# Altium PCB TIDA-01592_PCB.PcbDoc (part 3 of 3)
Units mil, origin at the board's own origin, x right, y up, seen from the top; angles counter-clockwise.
Board outline 2047.24 x 4291.34 mil, 4 copper layers (Top Layer, GND, PWR, Bottom Layer), stack 61.6 mil thick; 218 components, 89 nets, 503 pads, 366 vias.
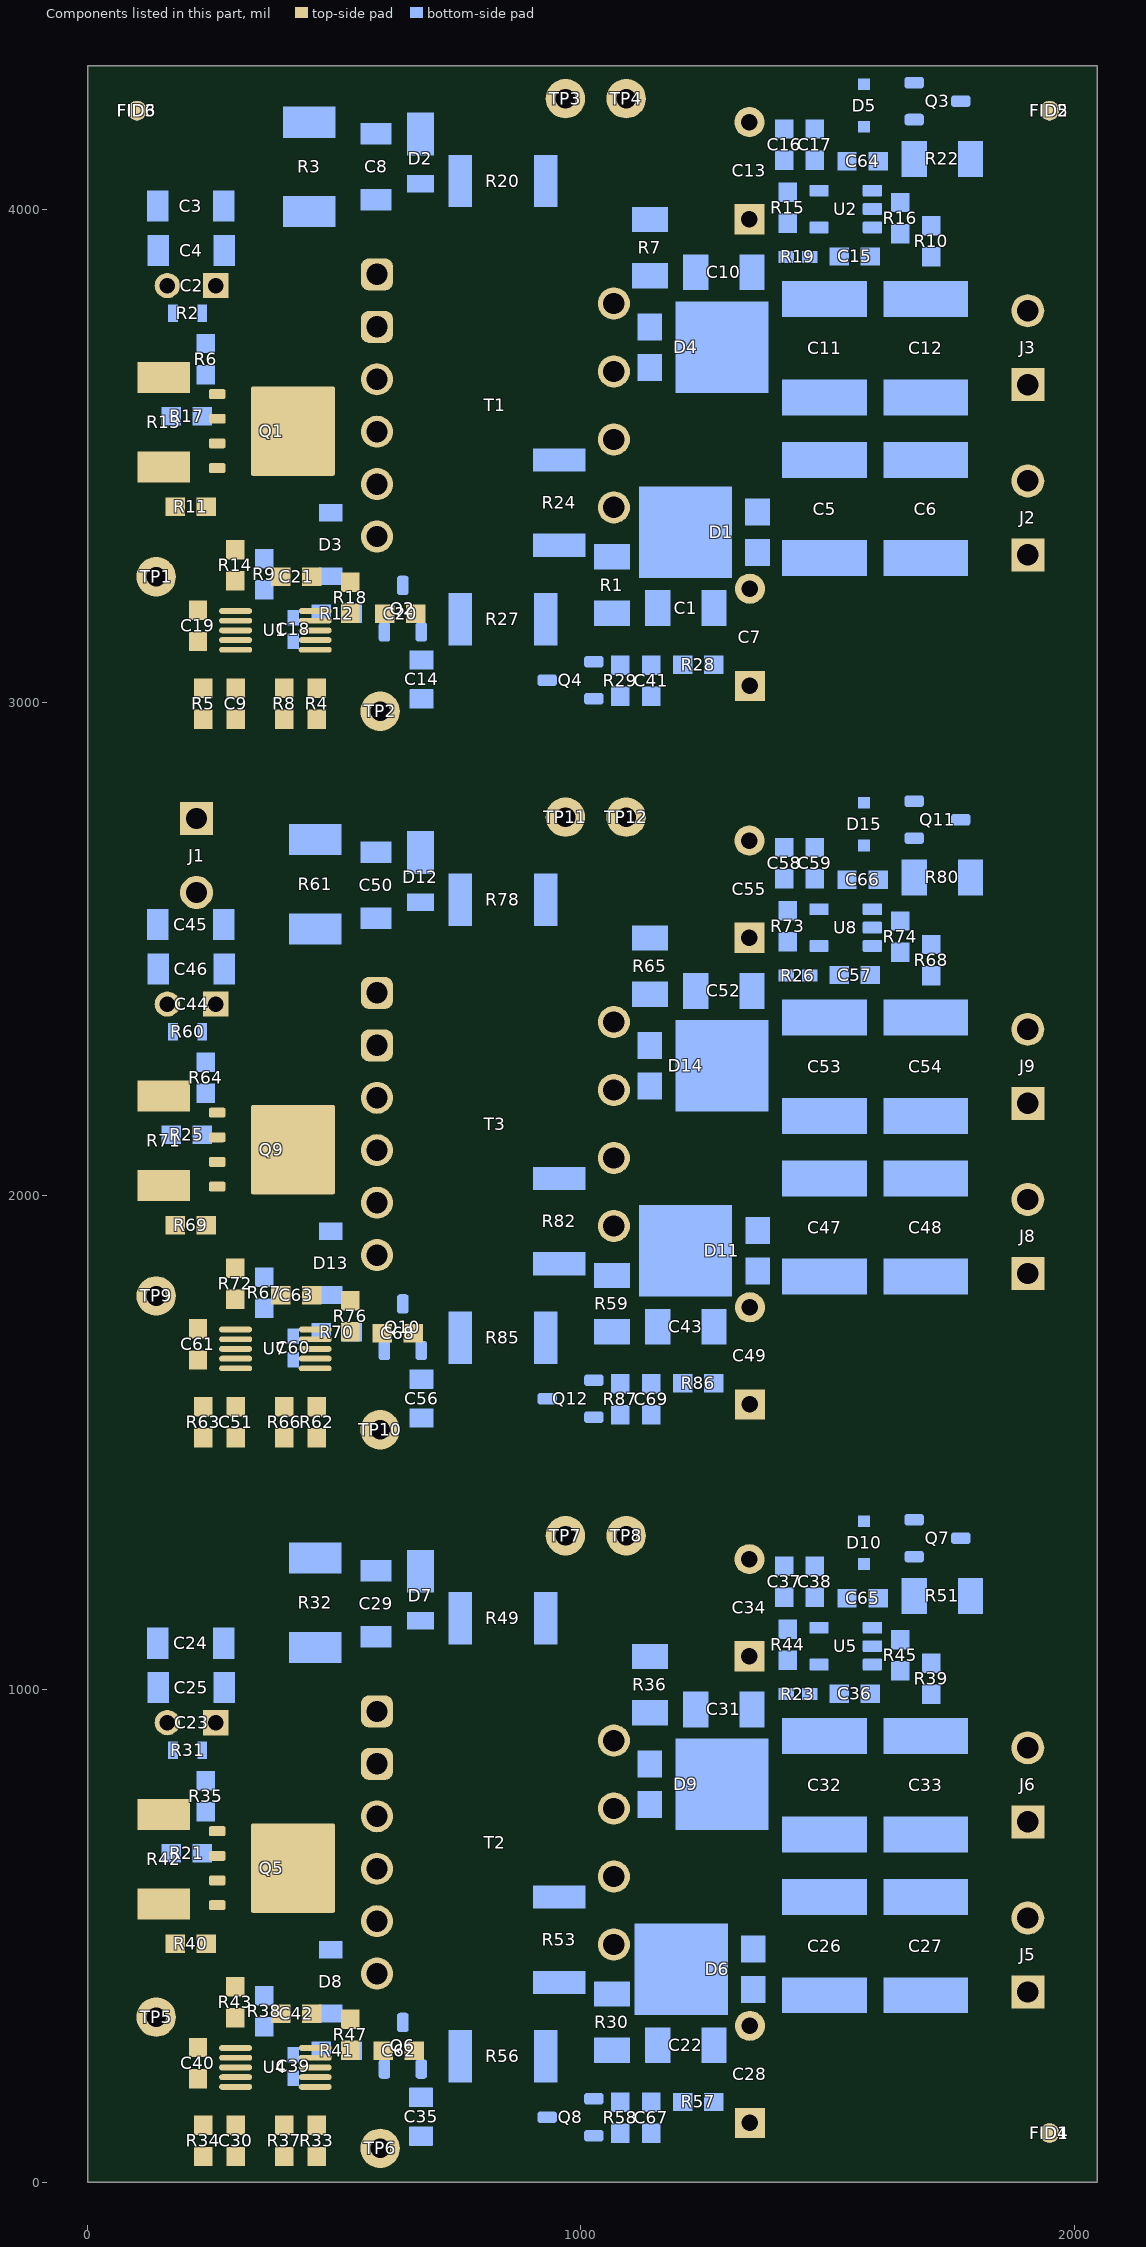
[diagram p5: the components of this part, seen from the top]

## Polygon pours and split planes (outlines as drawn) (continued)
+Vo2 on Bottom Layer "Bottom Layer-No Net 1" (solid, remove dead copper, pour order 1138): 1184,2173.69 1192,2165.69 1376,2165.69 1383,2172.69 1383,2195 1417,2229 1790.69,2229 1881,2138.69 1995.69,2138.69 2044,2187 2044,2391.69 1968.69,2467 1680.31,2467 1619,2405.69 1444,2405.69 1393,2456.69 1320,2456.69 1312,2448.69 1312,2369.69 1303,2360.69 1189,2360.69 1184,2355.69
NetC43_1 on Bottom Layer "Bottom Layer-No Net 6" (solid, remove dead copper, pour order 1134): 1320,1798.69 1296,1774.69 1243,1774.69 1237,1768.69 1237,1692.69 1245,1684.69 1979,1684.69 2013,1718.69 2013,2000.69 1985,2028.69 1882,2028.69 1816,1962.69 1326,1962.69 1320,1956.69
Vin on Bottom Layer "Bottom Layer-No Net 7" (solid, remove dead copper, pour order 1132): 1747,2620.69 1766,2601.69 1828,2601.69 1853,2626.69 1853,2752.69 1826,2779.69 1754,2779.69 1747,2772.69
PWRGND02 on Bottom Layer "Bottom Layer-No Net 9" (solid, remove dead copper, pour order 1130): 1002,1480.69 1008,1474.69 1155,1474.69 1169,1488.69 1169,1571.69 1162,1578.69 1010,1578.69 1002,1570.69
PWRGND01 on Bottom Layer "Bottom Layer-No Net 9" (solid, remove dead copper, pour order 736): 1002,24 1008,18 1155,18 1169,32 1169,115 1162,122 1010,122 1002,114
Vin on Bottom Layer "Bottom Layer-No Net 7" (solid, remove dead copper, pour order 734): 1747,1164 1766,1145 1828,1145 1853,1170 1853,1296 1826,1323 1754,1323 1747,1316
NetC22_1 on Bottom Layer "Bottom Layer-No Net 6" (solid, remove dead copper, pour order 728): 1320,342 1296,318 1243,318 1237,312 1237,236 1245,228 1979,228 2013,262 2013,544 1985,572 1882,572 1816,506 1326,506 1320,500
NetD6_3 on Bottom Layer "Bottom Layer-No Net 3" (solid, remove dead copper, pour order 516): 1031.74,341.26 1037,336 1289.28,336 1300,346.72 1300,519.13 1293.13,526 1040.74,526 1031.74,517
GND on Bottom Layer "Bottom Layer-No Net" (solid, remove dead copper, pour order 510): 194.74,795 190.74,791 95,791 89,797 89,1149 175,1149 194.74,1129.26
NetC29_2 on Bottom Layer "NETC29_2_L04_P508" (solid, remove dead copper, pour order 508): 398.74,1219 423.74,1194 702.74,1194 712.74,1204 712.74,1292 699.74,1305 415.74,1305 398.74,1288
NetC65_1 on Bottom Layer "Bottom Layer-No Net 8" (solid, remove dead copper, pour order 700): 1560,1233 1580,1213 1580,1164 1595,1149 1700,1149 1705,1154 1705,1269.85 1691.85,1283 1578,1283 1560,1265
+Vo1 on Bottom Layer "Bottom Layer-No Net 1" (solid, remove dead copper, pour order 1262): 1184,717 1192,709 1376,709 1383,716 1383,738.31 1417,772.31 1790.69,772.31 1881,682 1995,682 2044,731 2044,935 1968.69,1010.31 1680.31,1010.31 1619,949 1444,949 1393,1000 1320,1000 1312,992 1312,913 1303,904 1189,904 1184,899
PWRGND11 on Bottom Layer "Bottom Layer-No Net 4" (solid, remove dead copper, pour order 1264): 1373,693 1391.85,693 1407.15,708.31 1407.15,742.15 1412,747 1780.64,747 1799,728.64 1799,544 1780,525 1412,525 1383,554 1055,554 1033,576 1033,663 1063,693
+Vo3 on Bottom Layer "Bottom Layer-No Net 1" (solid, remove dead copper, pour order 1266): 1184,3630.39 1192,3622.39 1376,3622.39 1383,3629.39 1383,3651.69 1417,3685.69 1790.69,3685.69 1881,3595.39 1994.39,3595.39 2044,3645 2044,3848.39 1968.69,3923.69 1680.31,3923.69 1619,3862.39 1444,3862.39 1393,3913.39 1320,3913.39 1312,3905.39 1312,3826.39 1303,3817.39 1189,3817.39 1184,3812.39
PWRGND13 on Bottom Layer "Bottom Layer-No Net 4" (solid, remove dead copper, pour order 1268): 1373,3606.39 1391.85,3606.39 1407.15,3621.69 1407.15,3655.54 1412,3660.39 1780.64,3660.39 1799,3642.02 1799,3457.39 1780,3438.39 1412,3438.39 1383,3467.39 1055,3467.39 1033,3489.39 1033,3576.39 1063,3606.39
GND on GND "Bottom Layer-No Net 10" (solid, remove dead copper, pour order 1226): 172,958 188,942 188,921 173,906 29,906 0,935 0,3864 8,3872 174,3872 187,3859 187,3832 174,3819 85,3819 81,3815 81,2813 87,2807 250,2807 266,2791 266,2736 246,2716 88,2716 81,2709 81,2418 84,2415 172,2415 188,2399 188,2378 172,2362 84,2362 81,2359 81,961 84,958
GND on GND "Bottom Layer-No Net" (solid, remove dead copper, pour order 1216): 193.37,3853.02 180.74,3840.39 15,3840.39 15,4220 84.71,4289.71 317.42,4289.71 340.37,4266.76 340.37,4180.76 324.37,4164.76 227.37,4164.76 193.37,4130.76 193.37,3976.76
GND on GND "GND-No Net" (solid, remove dead copper, pour order 1214): 797.74,2959.39 751.74,2913.39 130.74,2913.39 93,2951.13 93,3880.65 109.74,3897.39 185.74,3897.39 193.37,3889.76 193.37,3828.63 219,3803 756.12,3803 797.74,3761.39
GND on GND "Bottom Layer-No Net" (solid, remove dead copper, pour order 1162): 193.37,2396.32 180.74,2383.69 93,2383.69 93,2801 111.35,2819.35 331.08,2819.35 340.37,2810.06 340.37,2724.06 324.37,2708.06 227.37,2708.06 193.37,2674.06 193.37,2520.06
GND on GND "GND-No Net" (solid, remove dead copper, pour order 1160): 797.74,1502.69 751.74,1456.69 130.74,1456.69 93,1494.43 93,2423.95 109.74,2440.69 185.74,2440.69 193.37,2433.06 193.37,2370.63 218,2346 756.43,2346 797.74,2304.69
GND on GND "GND-No Net" (solid, remove dead copper, pour order 526): 797.74,46 751.74,0 130.74,0 93,37.74 93,967.26 109.74,984 185.74,984 193.37,976.37 193.37,915.63 219,890 755.74,890 797.74,848
GND on GND "GND-No Net 3" (solid, pour order 1212): 796,4252.13 796,3962.65 779.74,3946.39 656.74,3946.39 438.37,4164.76 324.37,4164.76 324.37,4269.33 331.08,4276.04 772.08,4276.04
PWRGND13 on GND "GND-No Net 4" (solid, pour order 1210): 888,3538.13 947.74,3478.39 1755,3478.39 1755,3593.39 1031.74,3593.39 1014.74,3610.39 1014.74,4139.39 988.74,4165.39 908.74,4165.39 888,4144.65
PWRGND13 on GND "GND-No Net 1" (solid, remove dead copper, pour order 1208): 1419,3571.93 1419,3133.39 1393,3107.39 1320,3107.39 1294,3081.39 1294,2958.39 1325,2927.39 1966,2927.39 2017,2978.39 2017,3302.39 1979,3340.39 1873,3340.39 1864,3331.39 1864,3056.39 1832,3024.39 1789,3024.39 1755,3058.39 1755,3571.93
PWRGND13 on GND "GND-No Net 2" (solid, remove dead copper, pour order 1206): 1419,3524.61 1419,4052.39 1292,4179.39 1292,4241.39 1319.61,4269 1977,4269 2047.24,4198.76 2047.24,3824.63 1964,3741.39 1885,3741.39 1857,3769.39 1857,4113.39 1842,4128.39 1793,4128.39 1755,4090.39 1755,3964.39 1755,3581.39 1755,3519.39
GND on GND "GND-No Net 3" (solid, pour order 1158): 796,2795.43 796,2505.95 779.74,2489.69 656.74,2489.69 438.37,2708.06 324.37,2708.06 324.37,2812.64 331.08,2819.35 772.08,2819.35
PWRGND12 on GND "GND-No Net 4" (solid, pour order 1156): 888,2081.43 947.74,2021.69 1755,2021.69 1755,2136.69 1031.74,2136.69 1014.74,2153.69 1014.74,2682.69 988.74,2708.69 908.74,2708.69 888,2687.95
PWRGND12 on GND "GND-No Net 1" (solid, remove dead copper, pour order 1154): 1419,2115.23 1419,1676.69 1393,1650.69 1320,1650.69 1294,1624.69 1294,1501.69 1325,1470.69 1966,1470.69 2017,1521.69 2017,1845.69 1979,1883.69 1873,1883.69 1864,1874.69 1864,1599.69 1832,1567.69 1789,1567.69 1755,1601.69 1755,2115.23
PWRGND11 on GND "GND-No Net 1" (solid, remove dead copper, pour order 730): 1419,658.54 1419,220 1393,194 1336,194 1305,163 1305,34 1325,14 1966,14 2017,65 2017,389 1979,427 1873,427 1864,418 1864,143 1832,111 1789,111 1755,145 1755,658.54
PWRGND11 on GND "GND-No Net 4" (solid, pour order 534): 888,624.74 947.74,565 1755,565 1755,680 1031.74,680 1014.74,697 1014.74,1226 988.74,1252 908.74,1252 888,1231.26
GND on GND "GND-No Net 3" (solid, pour order 532): 796,1338.74 796,1049.26 779.74,1033 656.74,1033 438.37,1251.37 324.37,1251.37 324.37,1355.95 331.08,1362.66 772.08,1362.66
GND on GND "Bottom Layer-No Net" (solid, remove dead copper, pour order 524): 193.37,939.63 180.74,927 93,927 93,1330 139.32,1376.32 317.42,1376.32 340.37,1353.37 340.37,1267.37 324.37,1251.37 227.37,1251.37 193.37,1217.37 193.37,1063.37
PWRGND12 on GND "GND-No Net 2" (solid, remove dead copper, pour order 1270): 1419,2067.92 1419,2595.69 1292,2722.69 1292,2784.69 1319.61,2812.31 1977,2812.31 2047.24,2742.06 2047.24,2367.94 1964,2284.69 1885,2284.69 1857,2312.69 1857,2656.69 1842,2671.69 1793,2671.69 1755,2633.69 1755,2507.69 1755,2124.69 1755,2062.69
PWRGND11 on GND "GND-No Net 2" (solid, remove dead copper, pour order 1272): 1419,611.23 1419,1139 1292,1266 1292,1328 1319.61,1355.61 1977,1355.61 2047.24,1285.37 2047.24,911.24 1964,828 1885,828 1857,856 1857,1200 1842,1215 1793,1215 1755,1177 1755,1051 1755,668 1755,606
NetD2_2 on PWR "Top Layer-No Net" (solid, pour order 1222): 337,3469.39 539.5,3266.89 750.5,3266.89 791,3307.39 791,3521.39 791,3765.39 744,3812.39 407,3812.39 337,3742.39
NetD12_2 on PWR "Top Layer-No Net" (solid, remove dead copper, pour order 1168): 337,2012.69 539.5,1810.19 750.5,1810.19 791,1850.69 791,2064.69 791,2308.69 744,2355.69 407,2355.69 337,2285.69
NetD7_2 on PWR "Top Layer-No Net" (solid, pour order 706): 337,556 539.5,353.5 750.5,353.5 791,394 791,608 791,852 744,899 407,899 337,829
+Vo3 on PWR "Bottom Layer-No Net 5" (solid, remove dead copper, pour order 1246): 1127,4071.39 1127,3636.38 1175,3588.39 1988,3588.38 2047.24,3647.63 2047.24,4062.15 1984.73,4124.65 1180.27,4124.65
NetD1_3 on PWR "Bottom Layer-No Net 3" (solid, remove dead copper, pour order 1244): 1031.74,2988.64 1107,2913.39 1951.01,2913.39 2047.2,3009.59 2047.21,3430.18 1988,3489.38 1092,3489.39 1031.74,3429.13
+Vo2 on PWR "Bottom Layer-No Net 5" (solid, remove dead copper, pour order 1242): 1127,2614.69 1127,2179.69 1175,2131.69 1988,2131.69 2047.24,2190.93 2047.24,2605.46 1984.73,2667.96 1180.27,2667.96
NetD11_3 on PWR "Bottom Layer-No Net 3" (solid, remove dead copper, pour order 1240): 1031.74,1531.95 1107,1456.7 1951.01,1456.7 2047.2,1552.9 2047.21,1973.48 1988,2032.69 1092,2032.69 1031.74,1972.43
Vin on PWR "PWR-No Net 2" (solid, remove dead copper, pour order 1230): 186,2579 229,2536 229,2366 240,2355 285,2355 292,2362 292,2616 252,2656 202,2656 186,2640
Vin on PWR "PWR-No Net" (solid, remove dead copper, pour order 1228): 230,904.62 235,899.62 287.62,899.62 292,904 292,1095 77,1310 77,2536 117,2576 251.91,2576 268,2592.09 268,2640 252,2656 128,2656 77,2707 77,3568 288,3779 288,4003.34 237.34,4054 59,4054 0,3995 0,1178 230,948
NetD6_3 on PWR "Bottom Layer-No Net 3" (solid, remove dead copper, pour order 684): 1031.74,75.26 1107,0 1951.01,0.01 2047.2,96.2 2047.21,516.79 1988,576 1092,576 1031.74,515.74
+Vo1 on PWR "Bottom Layer-No Net 5" (solid, remove dead copper, pour order 682): 1127,1158 1127,723 1175,675 1988,675 2047.24,734.24 2047.24,1148.76 1984.73,1211.27 1180.27,1211.27

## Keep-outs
Keep-Out Layer:
  lines w10: 124,1377.95 2047.24,1377.95 ; 131,2834.65 2047.24,2834.65 ; 0,0 0,4291.34 2047.24,4291.34 2047.24,0 0,0

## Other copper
Top Layer:
  text ".Layer_Name" at 505.74,-937.23 h60
GND:
  pour cut-out: 222,3075.39 334,2963.39 364,2963.39 383,2982.39 383,3016.39 291,3108.39 291,3268.39 275,3284.39 241,3284.39 222,3265.39
  pour cut-out: 222,1618.69 334,1506.69 364,1506.69 383,1525.69 383,1559.69 291,1651.69 291,1811.69 275,1827.69 241,1827.69 222,1808.69
  pour cut-out: 222,162 334,50 364,50 383,69 383,103 291,195 291,355 275,371 241,371 222,352
  text "'.Layer_Name'" at 510,-936 h60
PWR:
  text "'.Layer_Name'" at 508,-940 h60
Bottom Layer:
  text ".Layer_Name" at 505.74,-937.23 h60

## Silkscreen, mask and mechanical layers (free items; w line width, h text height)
Top Overlay:
  lines w6: 144.74,131 197.74,131 ; 144.74,1587.69 197.74,1587.69 ; 144.74,3044.39 197.74,3044.39 ; 148.74,8 425.74,8 432.74,15 ; 148.74,1464.69 425.74,1464.69 432.74,1471.69 ; 148.74,2921.39 425.74,2921.39 432.74,2928.39 ; 206.74,160 268.74,160 282.74,174 ; 206.74,1616.69 268.74,1616.69 282.74,1630.69 ; 206.74,3073.39 268.74,3073.39 282.74,3087.39
  text "TIDA-01592-E1" at 193,4202 h90
  text "RoHS Exempt" at 318,4142 h60
  text "GND" at 1098,4038.39 h25 r90
  text "VCONT3" at 982,4013 h25 r90
  text "PGND" at 1622,3786 h30
  text "+100V Max" at 1474,3623 h30
  text "-100V Max" at 1479,3429 h30
  text "PGND" at 1624,3279 h30
  text "SYNC3" at 73,3199 h25 r90
  text "GND" at 687,2951.39 h25 r90
  text "GND" at 391,2765 h30
  text "High  / Voltage / Danger" at 1543.5,2756.94 h30
  text "24VDC" at 390,2632 h30
  text "GND" at 1098,2581.69 h25 r90
  text "VIN" at 431,2576 h30
  text "VCONT2" at 982,2556.31 h25 r90
  text "PGND" at 1625,2326 h30
  text "+100V Max" at 1486,2179 h30
  text "-100V Max" at 1485,1973 h30
  text "PGND" at 1627,1828 h30
  text "SYNC2" at 72,1736 h25 r90
  text "GND" at 687,1494.69 h25 r90
  text "High  / Voltage / Danger" at 1552.5,1309.94 h30
  text "GND" at 1098,1125 h25 r90
  text "VCONT1" at 982,1099.61 h25 r90
  text "PGND" at 1618,864 h30
  text "+100V Max" at 1487,714 h30
  text "-100V Max" at 1481,518 h30
  text "PGND" at 1627,364 h30
  text "SYNC1" at 75,292 h25 r90
  text "GND" at 687,38 h25 r90
  text ".Layer_Name" at 505.74,-937.23 h60
Bottom Overlay:
  lines w6: 1095,218 1103,210 1236,210 1248,222 1415,222 ; 1095,1674.69 1103,1666.69 1236,1666.69 1248,1678.69 1415,1678.69 ; 1095,3131.39 1103,3123.39 1236,3123.39 1248,3135.39 1415,3135.39 ; 1103,58 1147,14 1198,14 ; 1103,1514.69 1147,1470.69 1198,1470.69 ; 1103,2971.39 1147,2927.39 1198,2927.39 ; 1182,110 1257,110 1267,100 ; 1182,1566.69 1257,1566.69 1267,1556.69 ; 1182,3023.39 1257,3023.39 1267,3013.39 ; 1188,1243 1248,1243 1344,1147 1377,1147 ; 1188,2699.69 1248,2699.69 1344,2603.69 1377,2603.69 ; 1188,4156.39 1248,4156.39 1344,4060.39 1377,4060.39 ; 1223,1119 1287,1055 1287,1042 1305,1024 1378,1024 1386,1016 ; 1223,2575.69 1287,2511.69 1287,2498.69 1305,2480.69 1378,2480.69 1386,2472.69 ; 1223,4032.39 1287,3968.39 1287,3955.39 1305,3937.39 1378,3937.39 1386,3929.39 ; 1503,1315 1503,1301 1521,1283 1521,1222 ; 1503,2771.69 1503,2757.69 1521,2739.69 1521,2678.69 ; 1503,4228.39 1503,4214.39 1521,4196.39 1521,4135.39 ; 1584.74,3863.39 1607.74,3886.39 1607.74,3938.39
  text ".Layer_Name" at 505.74,-937.23 h60
Top Paste:
  text ".Layer_Name" at 505.74,-937.23 h60
Bottom Paste:
  text ".Layer_Name" at 505.74,-937.23 h60
Top Solder:
  text ".Layer_Name" at 505.74,-937.23 h60
  text ".Layer_Name" at 505.74,-937.23 h60
Bottom Solder:
  text ".Layer_Name" at 505.74,-937.23 h60
Drill Guide:
  text ".Layer_Name" at 505.74,-937.23 h60
M1 Board Outline:
  the board outline again, w10
M2 Board Dimensions:
  rectangle: 53.74,-478.74 428.74,-353.74
  rectangle: -71.26,-353.74 53.74,-228.74
  lines w7: -71.26,-353.74 928.74,-353.74 ; 53.74,-478.74 53.74,-228.74 ; 178.74,-478.74 178.74,-228.74 ; 428.74,-478.74 428.74,-228.74 ; 678.74,-478.74 678.74,-228.74 ; -71.26,-478.74 -71.26,-228.74 928.74,-228.74 928.74,-478.74 -71.26,-478.74
M3 3D STEP Top:
  text ".Layer_Name" at 505.74,-937.23 h60
M4 3D STEP Bottom:
  text ".Layer_Name" at 505.74,-937.23 h60
M5 Assembly Top:
  lines w10: -363.26,-1008.91 6236.74,-1008.91 ; -363.26,-805.57 6238.74,-805.57 ; -363.26,-602.24 -363.26,-1212.24 3641.74,-1212.24 6238.74,-1212.24 6238.74,-602.24 -362.76,-602.24 -362.76,-1212.24 1212.74,-1212.24 ; 2101.74,-1212.24 2101.74,-602.24 ; 3368.74,-805.57 3368.74,-602.24 ; 4208.74,-805.57 4208.74,-602.24 ; 4830.74,-1218.74 4830.74,-1015.91
  text "COMPONENTS MARKED 'DNP' SHOULD NOT BE POPULATED." at 1082.24,-397.24 h60
  text "ASSEMBLY VARIANT:" at 1081.74,-512.74 h60
  text ".VariantName" at 2117.74,-512.74 h60
  text "PCB VIEWED FROM TOP SIDE" at -299.76,-734.41 h60
  text "BOARD #:" at 2176.74,-734.41 h60
  text ".PRJ_Number" at 2722.24,-734.41 h60
  text "REV:" at 3566.74,-734.41 h60
  text ".PCB_Rev" at 3858.24,-734.41 h60
  text "SVN REV:" at 4404.74,-734.41 h60
  text ".VersionControl_RevNumber" at 4910.74,-734.41 h60
  text ".Layer_Name" at 511.74,-936.74 h60
  text "LAYER NAME =" at -300.26,-937.74 h60
  text "TID #:" at 2176.74,-937.74 h60
  text ".TID" at 2722.24,-937.74 h60
  text "PLOT NAME =" at -299.76,-1143.08 h60
  text ".plot_File_Name" at 505.74,-1143.08 h60
  text "GENERATED    :" at 2178.74,-1143.08 h60
  text ".Print_Date" at 3048.24,-1143.08 h60
  text ".Print_Time" at 3777.24,-1143.08 h60
  text "TEXAS INSTRUMENTS" at 5041.74,-1143.08 h60
M6 Assembly Bottom:
  lines w10: -363.76,-806.07 6238.24,-806.07 ; -361.76,-1009.41 6238.24,-1009.41 ; 1044.24,-1219.24 1044.24,-1016.41 ; 1666.24,-806.07 1666.24,-602.74 ; 2506.24,-806.07 2506.24,-602.74 ; 3773.24,-1212.74 3773.24,-602.74 ; 4662.24,-1212.74 6237.74,-1212.74 6237.74,-602.74 -363.76,-602.74 -363.76,-1212.74 2233.24,-1212.74 6238.24,-1212.74 6238.24,-602.74
  text "COMPONENTS MARKED 'DNP' SHOULD NOT BE POPULATED." at 6030.74,-396.74 h60
  text ".VariantName" at 4986.74,-512.74 h60
  text "ASSEMBLY VARIANT:" at 6025.74,-512.74 h60
  text ".VersionControl_RevNumber" at 964.24,-734.91 h60
  text "SVN REV:" at 1470.24,-734.91 h60
  text ".PCB_Rev" at 2016.74,-734.91 h60
  text "REV:" at 2308.24,-734.91 h60
  text ".PRJ_Number" at 3152.74,-734.91 h60
  text "BOARD #:" at 3698.24,-734.91 h60
  text "PCB VIEWED FROM BOTTOM SIDE" at 6174.74,-734.91 h60
  text ".Layer_Name" at 5280.74,-936.74 h60
  text ".TID" at 3152.74,-938.24 h60
  text "TID #:" at 3698.24,-938.24 h60
  text "LAYER NAME =" at 6127.74,-942.74 h60
  text "TEXAS INSTRUMENTS" at 833.24,-1143.58 h60
  text ".Print_Time" at 2097.74,-1143.58 h60
  text ".Print_Date" at 2826.74,-1143.58 h60
  text "GENERATED    :" at 3696.24,-1143.58 h60
  text ".plot_File_Name" at 5369.24,-1143.58 h60
  text "PLOT NAME =" at 6174.74,-1143.58 h60
M9 Title Sheet:
  drawing of 57 lines, arcs and shapes, not listed
  text "1" at 668.58,7957.76 h70
  text "2" at 3164.24,7957.76 h70
  text "3" at 5653.58,7957.76 h70
  text "4" at 8160.25,7957.76 h70
  text "5" at 10659.24,7957.76 h70
  text "6" at 13164.24,7957.76 h70
  text "A" at -487.76,6814.76 h70
  text "A" at 14312.24,6814.76 h70
  text "B" at -487.76,4434.76 h70
  text "B" at 14312.24,4434.76 h70
  text "C" at -487.76,2059.76 h70
  text "C" at 14312.24,2059.76 h70
  text "PROJECT TITLE:" at 11272.24,198.76 h45
  text ".PRJ_Title" at 11322.24,65.43 h50
  text "DESIGNED FOR:" at 11272.24,-102.24 h45
  text ".PRJ_Customer" at 11322.24,-242.24 h70
  text "D" at -487.76,-310.24 h70
  text "D" at 14312.24,-310.24 h70
  text "FILE NAME:" at 11272.24,-402.24 h45
  text ".PCB_File_Name_No_Path" at 11322.24,-522.24 h70
  text "Texas Instruments (TI) and/or its licensors do not warrant the accuracy or completeness of this specification" at 6302.74,-684.08 h45
  text "ENGINEER:" at 11272.24,-692.24 h45
  text "LAYOUT BY:" at 12777.24,-692.24 h45
  text "or any information contained therein. TI and/or its licensors do not warrant that this design will meet" at 6257.75,-796.74 h45
  text ".PRJ_Engineer" at 11322.24,-847.23 h70
  text ".PCB_Layout" at 12827.74,-847.23 h70
  text "the specifications, will be suitable for your application or fit for any particular purpose, or will operate in" at 6257.75,-909.41 h45
  text "ALTIUM DESIGNER VERSION:" at 12777.24,-1002.24 h45
  text "an implementation. TI and/or its licensors do not warrant that the design is production worthy. You should" at 6257.75,-1022.07 h45
  text "completely validate and test your design implementation to confirm the system functionality for your application." at 6302.74,-1134.74 h45
  text ".print_Scale" at 11322.24,-1135.57 h70
  text ".Application_BuildNumber" at 12827.74,-1135.57 h70
  text "1" at 668.58,-1342.24 h70
  text "2" at 3164.24,-1342.24 h70
  text "3" at 5653.58,-1342.24 h70
  text "4" at 8160.25,-1342.24 h70
  text "5" at 10659.24,-1342.24 h70
  text "6" at 13164.24,-1342.24 h70
M10 Fab Notes:
  drawing of 173 lines, arcs and shapes, not listed
  text "DESIGN INFORMATION" at 12306.76,6122.26 h60
  text "8" at 12737,5943 h60
  text "MIN. TRACK WIDTH:" at 11662.2,5942.26 h60
  text "MIL" at 12913.2,5942.26 h60
  text "MIN. CLEARANCE:" at 11662.2,5810.26 h60
  text "0.2" at 12698.44,5810.26 h60
  text "mm" at 12913.2,5810.26 h60
  text "MIN. VIA PAD SIZE:" at 11662.2,5678.26 h60
  text "24" at 12729,5678 h60
  text "MIL" at 12913.2,5678.26 h60
  text "0.15mm (5.91MIL)" at 12357.2,5536.55 h60
  text "MINIMUM ANNULAR RING" at 11332.97,5532.26 h60
  text "EXTERNAL" at 13114.74,5532.26 h60
  text "PER" at 11532.97,5414.26 h60
  text "IPC-D-275 CLASS 2 LEVEL C" at 11752.97,5414.26 h60
  text "MIL, HOLES" at 13241.2,5301.97 h60
  text "+/-" at 12848.74,5301.26 h60
  text "+/-" at 13702.74,5301.26 h60
  text "REGISTRATION TOLERANCES:" at 11332.97,5296.26 h60
  text "METAL" at 12532.74,5296.26 h60
  text "5" at 13108.94,5296.26 h60
  text "3" at 13941.94,5296.26 h60
  text "MIL" at 14058.2,5296.26 h60
  text "+/-" at 13702.74,5183.26 h60
  text "HOLE SIZE TOLERANCE (UNLESS OTHERWISE SPECIFIED):" at 11332.97,5178.26 h60
  text "3" at 13941.94,5178.26 h60
  text "MIL" at 14058.2,5178.26 h60
  text "MATERIAL:" at 11258.2,4968.8 h60
  text "FR-4 High Tg" at 12244.64,4828.47 h60
  text "FR-408" at 11679.2,4819.9 h60
  text "OTHER" at 13167.2,4819.9 h60
  text "X" at 12089.74,4816.26 h60
  text "63 MIL (1.6mm) +/-10%" at 11999.3,4657.18 h60
  text "THICKNESS:" at 11332.97,4652.9 h60
  text "X" at 11871.14,4652.9 h60
  text "OTHER" at 13284.2,4652.9 h60
  text "TOLERANCE:" at 11332.97,4494.9 h60
  text "X" at 12172.27,4494.9 h60
  text "ANSI IPC-6012 TYPE 3 CLASS 2" at 12359.22,4494.9 h60
  text "OTHER +/-" at 12359.2,4338.9 h60
  text "BOW & TWIST:" at 11332.97,4181.9 h60
  text "X" at 12172.27,4181.9 h60
  text "ANSI IPC-6012 TYPE 3 CLASS 2" at 12359.22,4181.9 h60
  text "OTHER +/-" at 12359.2,4023.39 h60
  text "DRILLING:" at 11258.2,3884.9 h60
  text "REFERENCE:" at 11332.97,3767.9 h60
  text "X" at 11981.2,3767.9 h60
  text "AS SHOWN" at 12168.2,3767.9 h60
  text "X" at 12882.2,3767.9 h60
  text "NC_DRILL FILES" at 13019.2,3767.9 h60
  text "PTH COPPER THICKNESS:" at 11332.97,3609.9 h60
  text "X" at 12463.2,3609.9 h60
  text "20-30 um" at 12600.2,3609.9 h60
  text "OTHER" at 13317.2,3609.9 h60
  text "BOARD FINISH:" at 11258.2,3450.9 h60
  text "SILKSCREEN:" at 11413.42,3332.9 h60
  text "X" at 12362.2,3332.9 h60
  text "TOP" at 12488.2,3332.9 h60
  text "X" at 12872.2,3332.9 h60
  text "BOTTOM" at 12999.2,3332.9 h60
  text "SILKSCREEN COLOR:" at 11413.42,3165.9 h60
  text "X" at 12361.16,3165.9 h60
  text "WHITE" at 12488.2,3165.9 h60
  text "OTHER" at 12999.2,3165.9 h60
  text "X" at 12492.16,3006.7 h60
  text "GREEN" at 12619.2,3006.7 h60
  text "OTHER" at 13237.2,3006.7 h60
  text "SOLDER RESIST COLOR:" at 11413.42,2995.9 h60
  text "X" at 12492.16,2836.7 h60
  text "MATTE" at 12619.2,2836.7 h60
  text "SEMI-GLOSS" at 13236.74,2836.06 h60
  text "IMMERSION GOLD (ENIG)" at 12319.2,2648.18 h60
  text "ENEPIG" at 13656.74,2644.9 h60
  text "SURFACE FINISH:" at 11258.2,2643.9 h60
  text "X" at 12132.25,2643.9 h60
  text "IMM. TIN/SILVER OR EQUIV" at 11587.74,2486.9 h60
  text "OTHER" at 13019.2,2486.9 h60
  text "ARRAY/PANEL:" at 11258.2,2307.9 h60
  text "CUT AND TRIM PER M1 BOARD OUTLINE" at 12319.2,2303.61 h60
  text "N.C. ROUTE" at 12319.2,2151.9 h60
  text "X" at 12998.2,2151.9 h60
  text "V. SCORE" at 13185.2,2151.9 h60
  text "CERTIFICATION:" at 11258.2,2014.9 h60
  text "MATERIALS AND WORKMANSHIP FOR ALL PCBS" at 11983.2,2014.9 h60
  text "TO MEET OR EXCEED THE REQUIREMENTS OF:" at 11983.2,1916.9 h60
  text "X" at 11609.7,1780.39 h60
  text "ANSI IPC-A-600F CLASS ->" at 11748.7,1780.39 h60
  text "X" at 13387.76,1780.39 h60
  text "2" at 13506.7,1780.39 h60
  text "1" at 13191.7,1778.9 h60
  text "3" at 13860.7,1778.9 h60
  text "X" at 12423.76,1620.9 h60
  text "RoHS" at 12560.7,1620.9 h60
  text "OTHER" at 13205.1,1620.9 h60
  text "PER ORDER" at 13602.16,1620.9 h60
  text "ALL BOARDS MUST MEET OR EXCEED UL94-V0 REQUIREMENTS." at 11285.74,1455.26 h60
  text "PCB MUST BEAR THE UL94V-0 UL REGISTERED MATERIAL ID NUMBER" at 11285.74,1335.26 h60
  text "ADDITIONAL REQUIREMENTS:" at 11258.2,1161.9 h60
  text "MICROSECTION:" at 11332.97,1046.9 h60
  text "YES" at 12238.7,1046.9 h60
  text "REQUIRED" at 13100.2,890.75 h60
  text "BARE BOARD ELEC. TEST:" at 11332.97,887.9 h60
  text "NONE" at 12638.7,887.9 h60
  text "X" at 12973.2,887.9 h60
  text "PER ORDER" at 13692.2,887.9 h60
M11 Gerber Information:
  lines w10: -363.26,-1008.91 6236.74,-1008.91 ; -363.26,-805.57 6238.74,-805.57 ; -363.26,-602.24 -363.26,-1212.24 3641.74,-1212.24 6238.74,-1212.24 6238.74,-602.24 -362.76,-602.24 -362.76,-1212.24 1212.74,-1212.24 ; 2101.74,-1212.24 2101.74,-602.24 ; 3368.74,-805.57 3368.74,-602.24 ; 4208.74,-805.57 4208.74,-602.24 ; 4830.74,-1218.74 4830.74,-1015.91
  text "ALL ARTWORK VIEWED FROM TOP SIDE" at -299.76,-734.41 h60
  text "BOARD #:" at 2176.74,-734.41 h60
  text ".PRJ_Number" at 2722.24,-734.41 h60
  text "REV:" at 3566.74,-734.41 h60
  text ".PCB_Rev" at 3858.24,-734.41 h60
  text "SVN REV:" at 4404.74,-734.41 h60
  text ".VersionControl_RevNumber" at 4910.74,-734.41 h60
  text "LAYER NAME =" at -299.76,-937.23 h60
  text "TID #:" at 2176.74,-937.74 h60
  text ".TID" at 2722.24,-937.74 h60
  text "PLOT NAME =" at -299.76,-1143.08 h60
  text ".plot_File_Name" at 505.74,-1143.08 h60
  text "GENERATED    :" at 2178.74,-1143.08 h60
  text ".Print_Date" at 3048.24,-1143.08 h60
  text ".Print_Time" at 3777.24,-1143.08 h60
  text "TEXAS INSTRUMENTS" at 5041.74,-1143.08 h60
M12 Stackup:
  drawing of 295 lines, arcs and shapes, not listed
  text "Layer" at 9642.24,7703.76 h60
  text "Name" at 10052.15,7703.76 h60
  text "Material" at 10981.9,7703.76 h60
  text "Thickness" at 11841.66,7703.76 h60
  text "Constant" at 12491.5,7703.76 h60
  text "Board Layer Stack" at 13061.36,7703.76 h60
  text "1" at 9642.24,7583.76 h60
  text "Top Overlay" at 10052.15,7583.76 h60
  text "2" at 9642.24,7463.76 h60
  text "Top Solder" at 10052.15,7463.76 h60
  text "Solder Resist" at 10981.9,7463.76 h60
  text "0.40mil" at 11841.66,7463.76 h60
  text "3.5" at 12491.5,7463.76 h60
  text "3" at 9642.24,7343.76 h60
  text "Top Layer" at 10052.15,7343.76 h60
  text "Copper" at 10981.9,7343.76 h60
  text "1.40mil" at 11841.66,7343.76 h60
  text "4" at 9642.24,7223.76 h60
  text "Dielectric 1" at 10052.15,7223.76 h60
  text "FR-4 High Tg" at 10981.9,7223.76 h60
  text "10.00mil" at 11841.66,7223.76 h60
  text "4.2" at 12491.5,7223.76 h60
  text "5" at 9642.24,7103.76 h60
  text "GND" at 10052.15,7103.76 h60
  text "Copper" at 10981.9,7103.76 h60
  text "1.40mil" at 11841.66,7103.76 h60
  text "6" at 9642.24,6983.76 h60
  text "Dielectric 2" at 10052.15,6983.76 h60
  text "FR-4 High Tg" at 10981.9,6983.76 h60
  text "36.00mil" at 11841.66,6983.76 h60
  text "4.2" at 12491.5,6983.76 h60
  text "7" at 9642.24,6863.76 h60
  text "PWR" at 10052.15,6863.76 h60
  text "Copper" at 10981.9,6863.76 h60
  text "1.40mil" at 11841.66,6863.76 h60
  text "8" at 9642.24,6743.76 h60
  text "Dielectric 3" at 10052.15,6743.76 h60
  text "FR-4 High Tg" at 10981.9,6743.76 h60
  text "10.00mil" at 11841.66,6743.76 h60
  text "4.2" at 12491.5,6743.76 h60
  text "9" at 9642.24,6623.76 h60
  text "Bottom Layer" at 10052.15,6623.76 h60
  text "Copper" at 10981.9,6623.76 h60
  text "1.40mil" at 11841.66,6623.76 h60
  text "10" at 9642.24,6503.76 h60
  text "Bottom Solder" at 10052.15,6503.76 h60
  text "Solder Resist" at 10981.9,6503.76 h60
  text "0.40mil" at 11841.66,6503.76 h60
  text "3.5" at 12491.5,6503.76 h60
  text "11" at 9642.24,6383.76 h60
  text "Bottom Overlay" at 10052.15,6383.76 h60
M13 Component Bodies Top:
  text ".Layer_Name" at 505.74,-937.23 h60
M14 Component Bodies Bottom:
  text ".Layer_Name" at 505.74,-937.23 h60
M15 Courtyards Top:
  text ".Layer_Name" at 505.74,-937.23 h60
M16 Courtyards Bottom:
  text ".Layer_Name" at 505.74,-937.23 h60
Drill Drawing:
  circle w10: c2650.99,1682.59 r33.33
  lines w10: 2617.66,1065.93 2634.32,1065.93 2650.99,1049.26 2667.66,1065.93 2684.32,1065.93 2667.66,1082.59 2684.32,1099.26 2667.66,1099.26 2650.99,1115.93 2634.32,1099.26 2617.66,1099.26 2634.32,1082.59 2617.66,1065.93 ; 2617.66,1215.93 2634.32,1215.93 2634.32,1199.26 2667.66,1199.26 2667.66,1215.93 2684.32,1215.93 2684.32,1249.26 2667.66,1249.26 2667.66,1265.93 2634.32,1265.93 2634.32,1249.26 2617.66,1249.26 2617.66,1215.93 ; 2617.66,1349.26 2684.32,1349.26 2684.32,1415.93 2617.66,1415.93 2617.66,1349.26 ; 2617.66,1565.93 2684.32,1565.93 2650.99,1499.26 2617.66,1565.93 ; 2617.66,1799.26 2650.99,1815.93 2684.32,1799.26 2667.66,1832.59 2684.32,1865.93 2650.99,1849.26 2617.66,1865.93 2634.32,1832.59 2617.66,1799.26 ; 2617.66,1949.26 2617.66,1965.93 2634.32,1982.59 2617.66,1999.26 2617.66,2015.93 2634.32,2015.93 2650.99,1999.26 2667.66,2015.93 2684.32,2015.93 2684.32,1999.26 2667.66,1982.59 2684.32,1965.93 2684.32,1949.26 2667.66,1949.26 2650.99,1965.93 2634.32,1949.26 2617.66,1949.26 ; 2630.99,1552.59 2670.99,1552.59 2650.99,1512.59 2630.99,1552.59
  lines w15: 2557.86,1004.26 7592.49,1004.26 ; 2557.86,2054.26 7592.49,2054.26 ; 3108.74,854.26 3108.74,2204.26 ; 3708.58,854.26 3708.58,2204.26 ; 4808.26,854.26 4808.26,2204.26 ; 5314.14,854.26 5314.14,2204.26 ; 6047.94,854.26 6047.94,2204.26 ; 2557.86,854.26 7592.49,854.26 7592.49,2204.26 2557.86,2204.26 2557.86,854.26
  text "Symbol" at 2647.86,2099.26 h72
  text "Count" at 3153.74,2099.26 h72
  text "Hole Size" at 3753.58,2099.26 h72
  text "Plated" at 4853.26,2099.26 h72
  text "Hole Type" at 5359.14,2099.26 h72
  text "Drill Layer Pair" at 6092.94,2099.26 h72
  text "6" at 3153.74,1949.26 h60
  text "31.50mil (0.800mm)" at 3753.58,1949.26 h60
  text "PTH" at 4853.26,1949.26 h60
  text "Round" at 5359.14,1949.26 h60
  text "Top Layer - Bottom Layer" at 6092.94,1949.26 h60
  text "12" at 3153.74,1799.26 h60
  text "33.47mil (0.850mm)" at 3753.58,1799.26 h60
  text "PTH" at 4853.26,1799.26 h60
  text "Round" at 5359.14,1799.26 h60
  text "Top Layer - Bottom Layer" at 6092.94,1799.26 h60
  text "12" at 3153.74,1649.26 h60
  text "40.00mil (1.016mm)" at 3753.58,1649.26 h60
  text "PTH" at 4853.26,1649.26 h60
  text "Round" at 5359.14,1649.26 h60
  text "Top Layer - Bottom Layer" at 6092.94,1649.26 h60
  text "14" at 3153.74,1499.26 h60
  text "43.31mil (1.100mm)" at 3753.58,1499.26 h60
  text "PTH" at 4853.26,1499.26 h60
  text "Round" at 5359.14,1499.26 h60
  text "Top Layer - Bottom Layer" at 6092.94,1499.26 h60
  text "18" at 3153.74,1349.26 h60
  text "15.00mil (0.381mm)" at 3753.58,1349.26 h60
  text "PTH" at 4853.26,1349.26 h60
  text "Round" at 5359.14,1349.26 h60
  text "Top Layer - Bottom Layer" at 6092.94,1349.26 h60
  text "30" at 3153.74,1199.26 h60
  text "43.31mil (1.100mm)" at 3753.58,1199.26 h60
  text "PTH" at 4853.26,1199.26 h60
  text "Round" at 5359.14,1199.26 h60
  text "Top Layer - Bottom Layer" at 6092.94,1199.26 h60
  text "348" at 3153.74,1049.26 h60
  text "12.00mil (0.305mm)" at 3753.58,1049.26 h60
  text "PTH" at 4853.26,1049.26 h60
  text "Round" at 5359.14,1049.26 h60
  text "Top Layer - Bottom Layer" at 6092.94,1049.26 h60
  text "440 Total" at 3153.74,899.26 h60
  text "DRILL TABLE" at 3029.74,683.26 h60
  text "FOR 12MIL DRILL +0/-12MIL" at 3028,566 h60
  text "FOR PTH DRILL +/-3MIL" at 3028,438 h60
  text "NOTE:" at 3025.74,250.26 h60
  text "This is not an Impedance controlled board." at 3023,134 h60
  text ".Layer_Name" at 505.74,-937.23 h60
M17 Embedded Cavity:
  text ".Layer_Name" at 505.74,-937.23 h60
M18 Embedded Assembly:
  text ".Layer_Name" at 505.74,-937.23 h60
M19 Embedded Keepout:
  text ".Layer_Name" at 505.74,-937.23 h60

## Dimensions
0,0 to 2047.24,0 on M2 Board Dimensions
-71.26,-478.74 to 928.74,-478.74 on M2 Board Dimensions
0,0 to 0,4291.34 on M2 Board Dimensions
